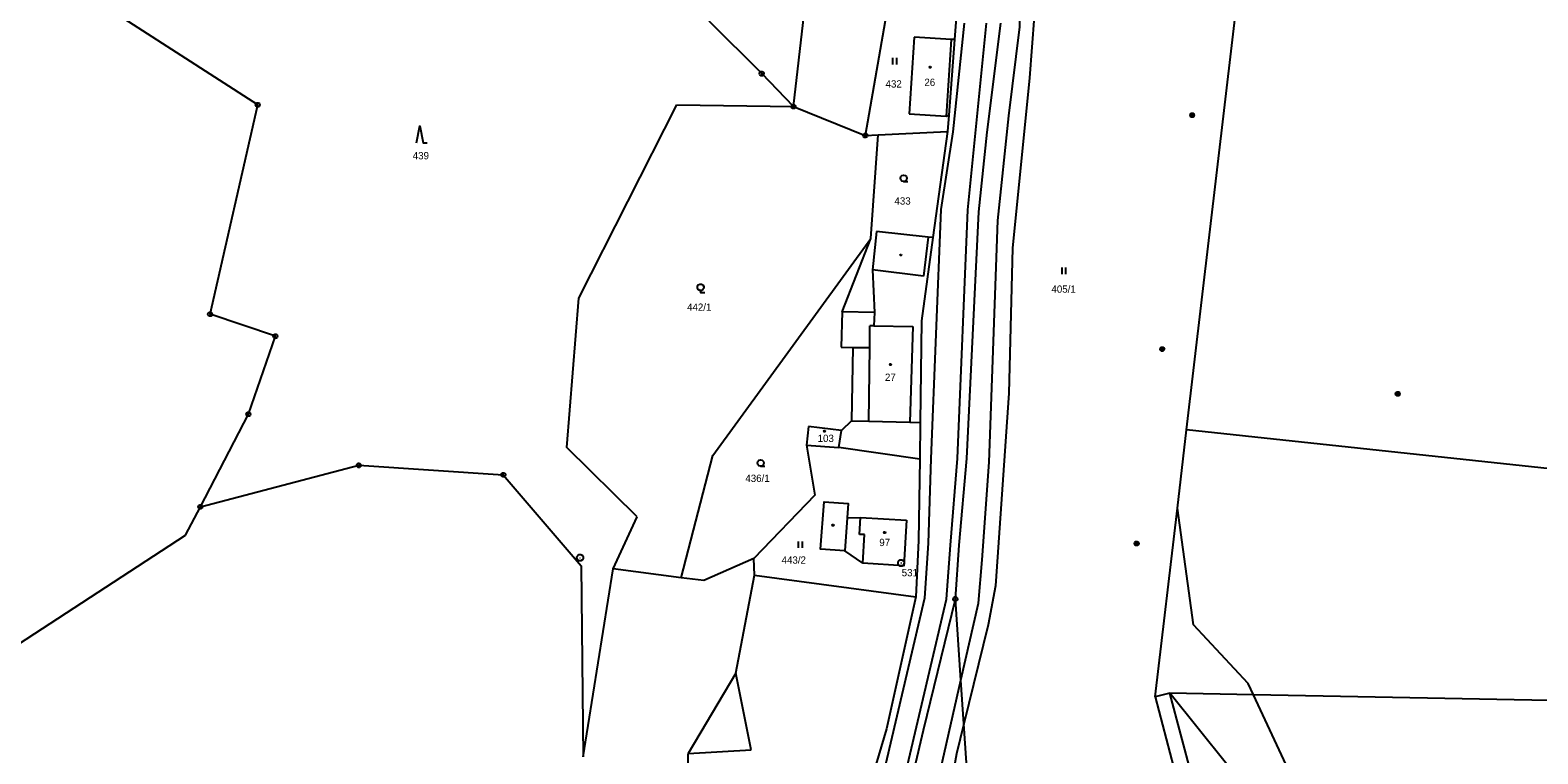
# Model space of a CAD drawing. Extents: x -694465 to -690527, y -983694 to -978978.
# Drawn here: x -693949.7 to -693597.5, y -981137 to -980968 of the extents above; entities that cross this region are included whole.
import ezdxf

# ---------------------------------------------------------------- set-up
doc = ezdxf.new("R2010")
doc.units = 0
for name, color, linetype in [('Vrstva 1', 7, 'Continuous'), ('Vrstva 17', 7, 'Continuous'), ('Vrstva 18', 7, 'Continuous'), ('Vrstva 19', 7, 'Continuous'), ('Vrstva 24', 7, 'Continuous'), ('Vrstva 25', 7, 'Continuous'), ('Vrstva 26', 7, 'Continuous')]:
    doc.layers.add(name, color=color, linetype=linetype)

msp = doc.modelspace()

# ---------------------------------------------------------------- linework, layer by layer
at = {"layer": 'Vrstva 1'}
for points in [[(-693710.479, -980876.975), (-693714.011, -980888.02), (-693715.716, -980897.686), (-693716, -980914.174), (-693715.148, -980964.777), (-693716.282, -980979.11), (-693720.26, -981018.91), (-693721.112, -981052.74), (-693724.231, -981097.731), (-693725.936, -981106.828), (-693731.6, -981129.933)], [(-693679.584, -981061.283), (-693658.09, -980879.08)], [(-693732.296, -981119.75), (-693728.224, -981101.757), (-693727.365, -981091.627), (-693725.66, -981068.884), (-693723.673, -981012.436), (-693721.116, -980987.987), (-693718.559, -980967.234), (-693718.841, -980952.837), (-693719.694, -980921.85), (-693719.978, -980902.519), (-693719.694, -980892.284), (-693718.261, -980886.191)], [(-693909.94, -981079.29), (-693898.7, -981057.64), (-693892.42, -981039.42), (-693907.68, -981034.31), (-693896.53, -980985.41), (-693943.43, -980955.15), (-693925.82, -980926.32), (-693919.28, -980903.3), (-693911.71, -980893.22), (-693900.91, -980893.1)], [(-693771.41, -980985.84), (-693761.19, -980897.2)], [(-693749.13, -980960.8), (-693754.62, -980992.61)], [(-693733.2, -980962.14), (-693733.81, -980970.2)], [(-693778.83, -980978.15), (-693791.13, -980965.91)], [(-693731.55, -980966.36), (-693734.15, -980991.74)], [(-693730.67, -981009.94), (-693726.35, -980966.38)], [(-693726.15, -980991.81), (-693722.99, -980966.35)], [(-693743.23, -980969.6), (-693744.38, -980987.53)], [(-693734.6, -980970.16), (-693743.23, -980969.6)], [(-693734.6, -980970.16), (-693735.75, -980988.09)], [(-693733.81, -980970.2), (-693735.14, -980987.85)], [(-693733.81, -980970.2), (-693734.6, -980970.16)], [(-693771.41, -980985.84), (-693778.83, -980978.15)], [(-693821.56, -981030.55), (-693798.62, -980985.43)], [(-693798.62, -980985.43), (-693771.41, -980985.84)], [(-693771.41, -980985.84), (-693754.62, -980992.61)], [(-693744.38, -980987.53), (-693735.75, -980988.09)], [(-693735.75, -980988.09), (-693735.14, -980987.85)], [(-693735.14, -980987.85), (-693735.43, -980991.68)], [(-693751.62, -980992.46), (-693735.43, -980991.68)], [(-693735.43, -980991.68), (-693738.83, -981016.41)], [(-693734.15, -980991.74), (-693736.99, -981009.85)], [(-693728.11, -981010.39), (-693726.15, -980991.81)], [(-693754.62, -980992.61), (-693751.62, -980992.46)], [(-693753.32, -981016.67), (-693751.62, -980992.46)], [(-693736.99, -981009.85), (-693739.31, -981068.09)], [(-693733.07, -981068.02), (-693730.67, -981009.94)], [(-693730.91, -981067.99), (-693728.11, -981010.39)], [(-693790.2, -981067.3), (-693753.32, -981016.67)], [(-693760.01, -981033.77), (-693753.32, -981016.67)], [(-693751.98, -981014.99), (-693752.96, -981023.99)], [(-693739.97, -981016.29), (-693751.98, -981014.99)], [(-693738.83, -981016.41), (-693741.51, -981035.89)], [(-693739.97, -981016.29), (-693741.01, -981025.43)], [(-693738.83, -981016.41), (-693739.97, -981016.29)], [(-693752.96, -981023.99), (-693752.49, -981033.93)], [(-693741.01, -981025.43), (-693752.96, -981023.99)], [(-693824.3, -981065.44), (-693821.56, -981030.55)], [(-693760.01, -981033.77), (-693760.25, -981042)], [(-693752.49, -981033.93), (-693760.01, -981033.77)], [(-693752.49, -981033.93), (-693752.6, -981037)], [(-693753.55, -981042.1), (-693753.6, -981036.996)], [(-693752.6, -981037), (-693753.6, -981036.996)], [(-693752.6, -981037), (-693743.49, -981037.19)], [(-693743.49, -981037.19), (-693744.2, -981059.51)], [(-693741.51, -981035.89), (-693741.8, -981059.56)], [(-693760.25, -981042), (-693757.5, -981042.05)], [(-693757.5, -981042.05), (-693757.81, -981059.2)], [(-693757.5, -981042.05), (-693753.55, -981042.1)], [(-693753.81, -981059.29), (-693753.55, -981042.1)], [(-693757.81, -981059.2), (-693760.18, -981061.44)], [(-693757.81, -981059.2), (-693753.81, -981059.29)], [(-693767.87, -981060.57), (-693768.38, -981064.9)], [(-693760.18, -981061.44), (-693767.87, -981060.57)], [(-693760.78, -981065.45), (-693760.18, -981061.44)], [(-693753.81, -981059.29), (-693744.2, -981059.51)], [(-693744.2, -981059.51), (-693741.8, -981059.56)], [(-693741.8, -981059.56), (-693741.91, -981068.16)], [(-693681.744, -981079.595), (-693679.584, -981061.283)], [(-693572.169, -981072.851), (-693679.584, -981061.283)], [(-693807.88, -981081.65), (-693824.3, -981065.44)], [(-693768.38, -981064.9), (-693766.42, -981076.55)], [(-693768.38, -981064.9), (-693760.78, -981065.45)], [(-693741.91, -981068.16), (-693760.78, -981065.45)], [(-693909.94, -981079.29), (-693872.9, -981069.59)], [(-693872.9, -981069.59), (-693839.17, -981071.84)], [(-693797.64, -981095.83), (-693790.2, -981067.3)], [(-693741.91, -981068.16), (-693742.22, -981087.15)], [(-693739.31, -981068.09), (-693739.97, -981087.77)], [(-693734.69, -981088.27), (-693733.07, -981068.02)], [(-693732.69, -981088.24), (-693730.91, -981067.99)], [(-693839.17, -981071.84), (-693821.02, -981093.03)], [(-693766.42, -981076.55), (-693780.65, -981091.34)], [(-694129.16, -981268.7), (-694143.47, -981229.56), (-694164.34, -981185.69), (-694173.45, -981169.83), (-694148.01, -981154.55), (-694105.53, -981141.09), (-694071.32, -981143.6), (-694046.38, -981139.79), (-694009.15, -981136.91), (-693980.91, -981128.58), (-693952.42, -981111.36), (-693913.39, -981085.93), (-693909.94, -981079.29)], [(-693759.44, -981089.55), (-693765.06, -981089.14), (-693764.25, -981078.12), (-693758.63, -981078.53), (-693758.88, -981081.83)], [(-693686.94, -981123.64), (-693681.744, -981079.595)], [(-693663.942, -981123.178), (-693665.165, -981120.555), (-693677.997, -981106.861), (-693681.744, -981079.595)], [(-693813.51, -981093.79), (-693807.88, -981081.65)], [(-693758.88, -981081.83), (-693759.44, -981089.55)], [(-693758.88, -981081.83), (-693755.74, -981081.81)], [(-693755.97, -981085.71), (-693755.74, -981081.81)], [(-693755.74, -981081.81), (-693745.03, -981082.43)], [(-693745.03, -981082.43), (-693745.65, -981093.04), (-693755.2, -981092.48)], [(-693754.81, -981085.78), (-693755.97, -981085.71)], [(-693755.2, -981092.48), (-693754.81, -981085.78)], [(-693742.22, -981087.15), (-693742.8, -981100.27)], [(-693755.2, -981092.48), (-693759.44, -981089.55)], [(-693739.97, -981087.77), (-693740.79, -981100.65)], [(-693735.67, -981100.83), (-693734.69, -981088.27)], [(-693733.59, -981100.81), (-693732.69, -981088.24)], [(-693821.02, -981093.03), (-693820.54, -981137.69)], [(-693820.54, -981137.69), (-693813.51, -981093.79)], [(-693797.64, -981095.83), (-693813.51, -981093.79)], [(-693780.65, -981091.34), (-693792.36, -981096.51)], [(-693780.53, -981095.22), (-693780.65, -981091.34)], [(-693792.36, -981096.51), (-693797.64, -981095.83)], [(-693784.84, -981118.1), (-693780.53, -981095.22)], [(-693780.53, -981095.22), (-693742.8, -981100.27)], [(-693740.79, -981100.65), (-693749.88, -981139.46)], [(-693742.8, -981100.27), (-693749.66, -981131.14)], [(-693745.07, -981140.92), (-693735.67, -981100.83)], [(-693741.01, -981131.44), (-693733.59, -981100.81)], [(-693732.296, -981119.75), (-693733.59, -981100.81)], [(-693784.84, -981118.1), (-693795.99, -981136.85)], [(-693781.28, -981136.05), (-693784.84, -981118.1)], [(-693741.01, -981175.956), (-693741.01, -981164.3), (-693738.453, -981146.958), (-693732.296, -981119.75)], [(-693731.6, -981129.933), (-693732.296, -981119.75)], [(-693683.51, -981122.8), (-693686.94, -981123.64)], [(-693686.94, -981123.64), (-693679.18, -981153.06)], [(-693663.942, -981123.178), (-693683.51, -981122.8)], [(-693637.2, -981180.54), (-693683.51, -981122.8)], [(-693675.75, -981151.74), (-693683.51, -981122.8)], [(-693586.77, -981124.67), (-693663.942, -981123.178)], [(-693637.2, -981180.54), (-693663.942, -981123.178)], [(-693749.66, -981131.14), (-693761.92, -981172.38)], [(-693751.25, -981174.9), (-693741.01, -981131.44)], [(-693731.6, -981129.933), (-693733.323, -981136.963), (-693736.733, -981156.01), (-693737.585, -981166.244), (-693737.585, -981177.331), (-693735.312, -981187.566), (-693733.862, -981195.729)], [(-693727.01, -981197.1), (-693731.6, -981129.933)], [(-693795.99, -981136.85), (-693781.28, -981136.05)], [(-693796.93, -981197.24), (-693795.99, -981136.85)]]:
    msp.add_lwpolyline(points, dxfattribs=at)
at = {"layer": 'Vrstva 24'}
for points in [[(-693778.676, -980977.674), (-693778.426, -980977.856), (-693778.33, -980978.15), (-693778.426, -980978.444), (-693778.676, -980978.626), (-693778.984, -980978.626), (-693779.234, -980978.444), (-693779.33, -980978.15), (-693779.234, -980977.856), (-693778.984, -980977.674)], [(-693896.376, -980984.934), (-693896.126, -980985.116), (-693896.03, -980985.41), (-693896.126, -980985.704), (-693896.376, -980985.886), (-693896.684, -980985.886), (-693896.934, -980985.704), (-693897.03, -980985.41), (-693896.934, -980985.116), (-693896.684, -980984.934)], [(-693771.256, -980985.364), (-693771.006, -980985.546), (-693770.91, -980985.84), (-693771.006, -980986.134), (-693771.256, -980986.316), (-693771.564, -980986.316), (-693771.814, -980986.134), (-693771.91, -980985.84), (-693771.814, -980985.546), (-693771.564, -980985.364)], [(-693754.466, -980992.134), (-693754.216, -980992.316), (-693754.12, -980992.61), (-693754.216, -980992.904), (-693754.466, -980993.086), (-693754.774, -980993.086), (-693755.024, -980992.904), (-693755.12, -980992.61), (-693755.024, -980992.316), (-693754.774, -980992.134)], [(-693907.526, -981033.834), (-693907.276, -981034.016), (-693907.18, -981034.31), (-693907.276, -981034.604), (-693907.526, -981034.786), (-693907.834, -981034.786), (-693908.084, -981034.604), (-693908.18, -981034.31), (-693908.084, -981034.016), (-693907.834, -981033.834)], [(-693892.266, -981038.944), (-693892.016, -981039.126), (-693891.92, -981039.42), (-693892.016, -981039.714), (-693892.266, -981039.896), (-693892.574, -981039.896), (-693892.824, -981039.714), (-693892.92, -981039.42), (-693892.824, -981039.126), (-693892.574, -981038.944)], [(-693898.546, -981057.164), (-693898.296, -981057.346), (-693898.2, -981057.64), (-693898.296, -981057.934), (-693898.546, -981058.116), (-693898.854, -981058.116), (-693899.104, -981057.934), (-693899.2, -981057.64), (-693899.104, -981057.346), (-693898.854, -981057.164)], [(-693872.746, -981069.114), (-693872.496, -981069.296), (-693872.4, -981069.59), (-693872.496, -981069.884), (-693872.746, -981070.066), (-693873.054, -981070.066), (-693873.304, -981069.884), (-693873.4, -981069.59), (-693873.304, -981069.296), (-693873.054, -981069.114)], [(-693839.016, -981071.364), (-693838.766, -981071.546), (-693838.67, -981071.84), (-693838.766, -981072.134), (-693839.016, -981072.316), (-693839.324, -981072.316), (-693839.574, -981072.134), (-693839.67, -981071.84), (-693839.574, -981071.546), (-693839.324, -981071.364)], [(-693909.786, -981078.814), (-693909.536, -981078.996), (-693909.44, -981079.29), (-693909.536, -981079.584), (-693909.786, -981079.766), (-693910.094, -981079.766), (-693910.344, -981079.584), (-693910.44, -981079.29), (-693910.344, -981078.996), (-693910.094, -981078.814)], [(-693821.046, -981090.436), (-693820.71, -981090.63), (-693820.516, -981090.966), (-693820.516, -981091.354), (-693820.71, -981091.69), (-693821.046, -981091.884), (-693821.434, -981091.884), (-693821.77, -981091.69), (-693821.964, -981091.354), (-693821.964, -981090.966), (-693821.77, -981090.63), (-693821.434, -981090.436)], [(-693746.056, -981091.676), (-693745.72, -981091.87), (-693745.526, -981092.206), (-693745.526, -981092.594), (-693745.72, -981092.93), (-693746.056, -981093.124), (-693746.444, -981093.124), (-693746.78, -981092.93), (-693746.974, -981092.594), (-693746.974, -981092.206), (-693746.78, -981091.87), (-693746.444, -981091.676)], [(-693733.436, -981100.334), (-693733.186, -981100.516), (-693733.09, -981100.81), (-693733.186, -981101.104), (-693733.436, -981101.286), (-693733.744, -981101.286), (-693733.994, -981101.104), (-693734.09, -981100.81), (-693733.994, -981100.516), (-693733.744, -981100.334)]]:
    msp.add_lwpolyline(points, close=True, dxfattribs=at)
for points in [[(-693778.949, -980978.15), (-693778.71, -980978.15)], [(-693896.649, -980985.41), (-693896.41, -980985.41)], [(-693771.529, -980985.84), (-693771.29, -980985.84)], [(-693754.739, -980992.61), (-693754.5, -980992.61)], [(-693907.799, -981034.31), (-693907.56, -981034.31)], [(-693892.539, -981039.42), (-693892.3, -981039.42)], [(-693898.819, -981057.64), (-693898.58, -981057.64)], [(-693873.019, -981069.59), (-693872.78, -981069.59)], [(-693839.289, -981071.84), (-693839.05, -981071.84)], [(-693910.059, -981079.29), (-693909.82, -981079.29)], [(-693821.29, -981091.16), (-693821.19, -981091.16)], [(-693746.3, -981092.4), (-693746.2, -981092.4)], [(-693733.709, -981100.81), (-693733.47, -981100.81)]]:
    msp.add_lwpolyline(points, dxfattribs=at)
at = {"layer": 'Vrstva 25'}
for points in [[(-693748.28, -980974.49), (-693748.28, -980975.99)], [(-693747.28, -980975.99), (-693747.28, -980974.49)], [(-693859.43, -980994.33), (-693858.68, -980990.33), (-693857.93, -980994.33), (-693856.93, -980994.33)], [(-693745.69, -981003.32), (-693746.065, -981003.219), (-693746.339, -981002.945), (-693746.44, -981002.57), (-693746.339, -981002.195), (-693746.065, -981001.921), (-693745.69, -981001.82), (-693745.315, -981001.921), (-693745.041, -981002.195), (-693744.94, -981002.57), (-693745.041, -981002.945), (-693745.315, -981003.219), (-693745.69, -981003.32), (-693744.69, -981003.321)], [(-693708.75, -981023.44), (-693708.75, -981024.94)], [(-693707.75, -981024.94), (-693707.75, -981023.44)], [(-693793.099, -981028.744), (-693793.294, -981028.744), (-693793.629, -981028.55), (-693793.824, -981028.214), (-693793.824, -981027.827), (-693793.631, -981027.49), (-693793.294, -981027.296), (-693792.907, -981027.296), (-693792.57, -981027.49), (-693792.376, -981027.825), (-693792.376, -981028.215), (-693792.569, -981028.55), (-693792.907, -981028.744), (-693793.099, -981028.744), (-693793.1, -981029.27), (-693792.099, -981029.268)], [(-693779.08, -981069.8), (-693779.455, -981069.699), (-693779.729, -981069.425), (-693779.83, -981069.05), (-693779.729, -981068.675), (-693779.455, -981068.401), (-693779.08, -981068.3), (-693778.705, -981068.401), (-693778.431, -981068.675), (-693778.33, -981069.05), (-693778.431, -981069.425), (-693778.705, -981069.699), (-693779.08, -981069.8), (-693778.08, -981069.801)], [(-693770.3, -981087.38), (-693770.3, -981088.88)], [(-693769.3, -981088.88), (-693769.3, -981087.38)]]:
    msp.add_lwpolyline(points, dxfattribs=at)
for points in [[(-693739.403, -980976.488), (-693739.315, -980976.64), (-693739.403, -980976.792), (-693739.577, -980976.792), (-693739.665, -980976.64), (-693739.577, -980976.488)], [(-693746.243, -981020.338), (-693746.155, -981020.49), (-693746.243, -981020.642), (-693746.417, -981020.642), (-693746.505, -981020.49), (-693746.417, -981020.338)], [(-693748.653, -981045.888), (-693748.565, -981046.04), (-693748.653, -981046.192), (-693748.827, -981046.192), (-693748.915, -981046.04), (-693748.827, -981045.888)], [(-693764.073, -981061.488), (-693763.985, -981061.64), (-693764.073, -981061.792), (-693764.247, -981061.792), (-693764.335, -981061.64), (-693764.247, -981061.488)], [(-693762.083, -981083.448), (-693761.995, -981083.6), (-693762.083, -981083.752), (-693762.257, -981083.752), (-693762.345, -981083.6), (-693762.257, -981083.448)], [(-693750.023, -981085.098), (-693749.935, -981085.25), (-693750.023, -981085.402), (-693750.197, -981085.402), (-693750.285, -981085.25), (-693750.197, -981085.098)]]:
    msp.add_lwpolyline(points, close=True, dxfattribs=at)
at = {"layer": 'Vrstva 26'}
for points in [[(-693678.435, -980987.364), (-693678.125, -980987.364), (-693677.875, -980987.546), (-693677.78, -980987.84), (-693677.875, -980988.134), (-693678.125, -980988.316), (-693678.435, -980988.316), (-693678.685, -980988.134), (-693678.78, -980987.84), (-693678.685, -980987.546), (-693678.435, -980987.364), (-693678.4, -980987.4), (-693678.16, -980987.4), (-693678, -980987.48), (-693678.56, -980987.48), (-693678.64, -980987.56), (-693677.92, -980987.56), (-693677.92, -980987.64), (-693678.64, -980987.64), (-693678.682, -980987.72), (-693677.88, -980987.721), (-693677.84, -980987.8), (-693678.72, -980987.8), (-693678.72, -980987.88), (-693677.84, -980987.88), (-693677.871, -980987.959), (-693678.685, -980987.959), (-693678.679, -980988.04), (-693677.871, -980988.04), (-693677.92, -980988.12), (-693678.64, -980988.12), (-693678.56, -980988.2), (-693678, -980988.2), (-693678.108, -980988.279), (-693678.448, -980988.279)], [(-693685.425, -981041.974), (-693685.115, -981041.974), (-693684.865, -981042.156), (-693684.77, -981042.45), (-693684.865, -981042.744), (-693685.115, -981042.926), (-693685.425, -981042.926), (-693685.675, -981042.744), (-693685.77, -981042.45), (-693685.675, -981042.156), (-693685.425, -981041.974), (-693685.39, -981042.01), (-693685.15, -981042.01), (-693684.99, -981042.09), (-693685.55, -981042.09), (-693685.63, -981042.17), (-693684.91, -981042.17), (-693684.91, -981042.25), (-693685.63, -981042.25), (-693685.672, -981042.33), (-693684.87, -981042.331), (-693684.83, -981042.41), (-693685.71, -981042.41), (-693685.71, -981042.49), (-693684.83, -981042.49), (-693684.861, -981042.569), (-693685.675, -981042.569), (-693685.669, -981042.65), (-693684.861, -981042.65), (-693684.91, -981042.73), (-693685.63, -981042.73), (-693685.55, -981042.81), (-693684.99, -981042.81), (-693685.098, -981042.889), (-693685.438, -981042.889)], [(-693685.425, -981041.974), (-693685.115, -981041.974), (-693684.865, -981042.156), (-693684.77, -981042.45), (-693684.865, -981042.744), (-693685.115, -981042.926), (-693685.425, -981042.926), (-693685.675, -981042.744), (-693685.77, -981042.45), (-693685.675, -981042.156), (-693685.425, -981041.974), (-693685.39, -981042.01), (-693685.15, -981042.01), (-693684.99, -981042.09), (-693685.55, -981042.09), (-693685.63, -981042.17), (-693684.91, -981042.17), (-693684.91, -981042.25), (-693685.63, -981042.25), (-693685.672, -981042.33), (-693684.87, -981042.331), (-693684.83, -981042.41), (-693685.71, -981042.41), (-693685.71, -981042.49), (-693684.83, -981042.49), (-693684.861, -981042.569), (-693685.675, -981042.569), (-693685.669, -981042.65), (-693684.861, -981042.65), (-693684.91, -981042.73), (-693685.63, -981042.73), (-693685.55, -981042.81), (-693684.99, -981042.81), (-693685.098, -981042.889), (-693685.438, -981042.889)], [(-693630.425, -981052.444), (-693630.115, -981052.444), (-693629.865, -981052.626), (-693629.77, -981052.92), (-693629.865, -981053.214), (-693630.115, -981053.396), (-693630.425, -981053.396), (-693630.675, -981053.214), (-693630.77, -981052.92), (-693630.675, -981052.626), (-693630.425, -981052.444), (-693630.39, -981052.48), (-693630.15, -981052.48), (-693629.99, -981052.56), (-693630.55, -981052.56), (-693630.63, -981052.64), (-693629.91, -981052.64), (-693629.91, -981052.72), (-693630.63, -981052.72), (-693630.672, -981052.8), (-693629.87, -981052.801), (-693629.83, -981052.88), (-693630.71, -981052.88), (-693630.71, -981052.96), (-693629.83, -981052.96), (-693629.861, -981053.039), (-693630.675, -981053.039), (-693630.669, -981053.12), (-693629.861, -981053.12), (-693629.91, -981053.2), (-693630.63, -981053.2), (-693630.55, -981053.28), (-693629.99, -981053.28), (-693630.098, -981053.359), (-693630.438, -981053.359)], [(-693691.405, -981087.384), (-693691.095, -981087.384), (-693690.845, -981087.566), (-693690.75, -981087.86), (-693690.845, -981088.154), (-693691.095, -981088.336), (-693691.405, -981088.336), (-693691.655, -981088.154), (-693691.75, -981087.86), (-693691.655, -981087.566), (-693691.405, -981087.384), (-693691.37, -981087.42), (-693691.13, -981087.42), (-693690.97, -981087.5), (-693691.53, -981087.5), (-693691.61, -981087.58), (-693690.89, -981087.58), (-693690.89, -981087.66), (-693691.61, -981087.66), (-693691.652, -981087.74), (-693690.85, -981087.741), (-693690.81, -981087.82), (-693691.69, -981087.82), (-693691.69, -981087.9), (-693690.81, -981087.9), (-693690.841, -981087.979), (-693691.655, -981087.979), (-693691.649, -981088.06), (-693690.841, -981088.06), (-693690.89, -981088.14), (-693691.61, -981088.14), (-693691.53, -981088.22), (-693690.97, -981088.22), (-693691.078, -981088.299), (-693691.418, -981088.299)]]:
    msp.add_lwpolyline(points, dxfattribs=at)

# ---------------------------------------------------------------- texts
at = {"layer": 'Vrstva 17'}
msp.add_text('531', height=1.7, dxfattribs=at).set_placement((-693746.123, -981095.51))
at = {"layer": 'Vrstva 18'}
for s, p in [('432', (-693749.895, -980981.39)), ('439', (-693860.333, -980998.14)), ('433', (-693747.818, -981008.72)), ('405/1', (-693711.149, -981029.3)), ('442/1', (-693796.259, -981033.52)), ('436/1', (-693782.642, -981073.48)), ('443/2', (-693774.174, -981092.56))]:
    msp.add_text(s, height=1.7, dxfattribs=at).set_placement(p)
at = {"layer": 'Vrstva 19'}
for s, p in [('26', (-693740.829, -980981.02)), ('27', (-693750.038, -981049.88)), ('103', (-693765.76, -981064.14)), ('97', (-693751.355, -981088.45))]:
    msp.add_text(s, height=1.7, dxfattribs=at).set_placement(p)

doc.saveas('drawing.dxf')
